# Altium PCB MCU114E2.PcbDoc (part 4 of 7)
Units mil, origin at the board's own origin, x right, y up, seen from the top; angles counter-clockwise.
Board outline 4153.94 x 2313.28 mil, 8 copper layers (Top Layer, GND 2, Signal Layer 3, Power 4, Power 5, Signal Layer 6, GND 7, Bottom), stack 61.2 mil thick; 444 components, 418 nets, 1811 pads, 981 vias.
Unrouted connection lines stored in the file: 3.
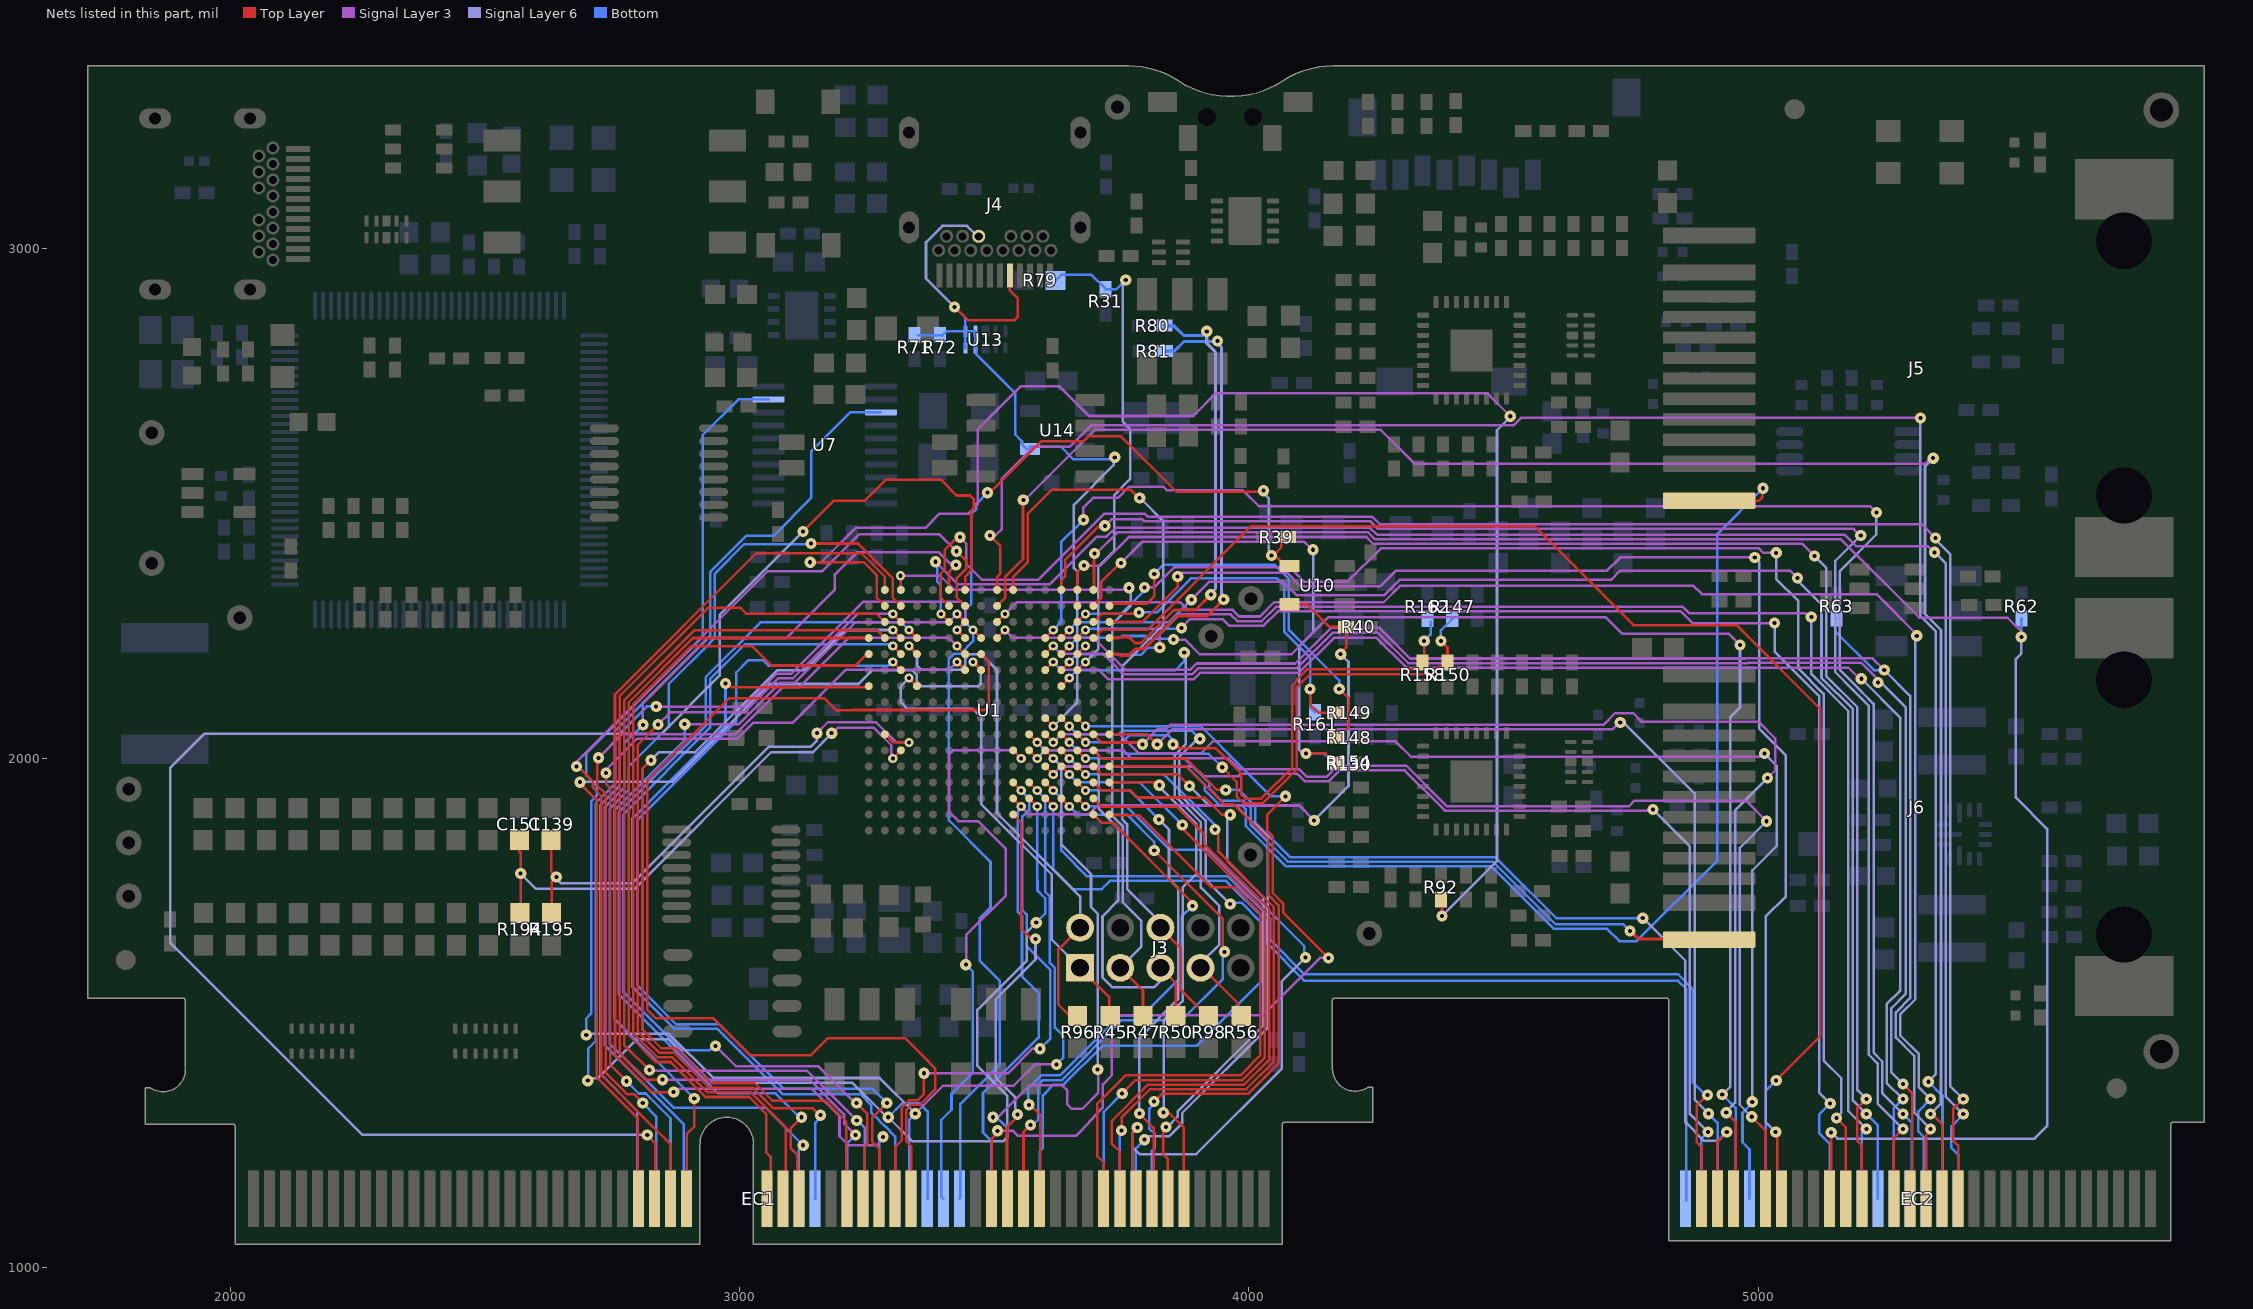
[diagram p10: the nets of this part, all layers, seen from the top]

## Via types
v1: diameter 22, hole 8, Top Layer to Bottom, tented both sides, 810 vias
v2: diameter 18, hole 8, Top Layer to Bottom, tented both sides, 153 vias
v3: diameter 19.68, hole 7.87, Top Layer to Bottom, tented both sides, 10 vias
v4: diameter 19.68, hole 7.87, Top Layer to Bottom, tented bottom, 4 vias
v5: diameter 19.68, hole 7.87, Top Layer to Bottom, tented top, 4 vias

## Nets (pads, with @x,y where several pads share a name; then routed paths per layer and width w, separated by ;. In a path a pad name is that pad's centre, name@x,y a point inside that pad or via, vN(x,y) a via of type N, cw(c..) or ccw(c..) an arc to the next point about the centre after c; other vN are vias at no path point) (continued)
MCU_C10C11_N: C139.1 R195.1 U1.K2 | length 1060.9
  Top Layer w4.9: C139.1@2630.06,1839.38 2630.06,1777.12 v1(2640.31,1766.88) 2631.04,1757.6 R195.1@2631.04,1695.94 ; U1.K2@3285.09,2047.04 3301.08,2031.06 v2(3332.6,2031.06)
  Signal Layer 3 w4.9: v1(3151.82,2049.25) 3173.14,2070.57 3268.21,2070.57 3307.73,2031.06 v2(3332.6,2031.06)
  Signal Layer 6 w4.9: v1(2640.31,1766.88) 2640.31,1763.7 2649.67,1754.34 2789.09,1754.34 3057.42,2022.67 3139.82,2022.67 3151.03,2033.89 3151.03,2048.47 v1(3151.82,2049.25)
MCU_C10C11_P: C151.1 R194.1 U1.L3 | length 1080.9
  Top Layer w4.9: C151.1@2567.97,1839.38 2567.97,1816.69 2570.31,1814.36 v1(2570.31,1773.88) 2570.31,1697.31 R194.1@2568.95,1695.94
  Top Layer w5: v2(3300.84,1999.8) U1.L3@3316.59,2015.55
  Signal Layer 3 w4.9: v1@3180.82,2048.25 3192.24,2059.67 3263.7,2059.67 3297.81,2025.56 3297.81,2009.22 3298.34,2008.69 3298.34,2003.35 3297.81,2002.83 v2(3300.84,1999.8)
  Signal Layer 6 w4.9: v1(2570.31,1773.88) 2600.74,1743.44 2793.61,1743.44 3061.94,2011.77 3144.34,2011.77 3180.82,2048.25 v1(3180.82,2049.25)
MCU_D_N: R81.2 U1.E16 | length 894.6
  Top Layer w6.1: U1.E16@3726.04,2204.52 3744.86,2204.52 3747.17,2202.22 3764.16,2202.22 3776.16,2214.22 3793.15,2214.22 3857.83,2278.9 3917.7,2278.9 v1(3950.26,2311.46)
  Signal Layer 6 w6.1: v1(3938,2819) 3938,2814.7 3946.29,2806.41 3946.29,2322.98 3947.22,2322.06 3947.22,2314.5 v1(3950.26,2311.46)
  Bottom w6.1: R81.2@3834.62,2799.19 3853.42,2799.19 3872.28,2818.04 3937.04,2818.04 v1(3938,2819)
MCU_D_P: R80.2 U1.D16 | length 866.5
  Top Layer w6.1: U1.D16@3726.04,2236.02 3745.16,2236.02 3747.46,2238.32 3764.16,2238.32 3776.16,2226.32 3788.14,2226.32 3852.82,2291 3895,2291 v1(3925,2321)
  Signal Layer 6 w6.1: v1(3917,2838) 3917,2814.47 3930.52,2800.95 3930.62,2800.95 3934.19,2797.38 3934.19,2332.52 3925,2323.33 v1(3925,2321)
  Bottom w6.1: R80.2@3833.62,2849 3852.42,2849 3871.28,2830.14 3909.14,2830.14 v1(3917,2838)
MCU_GPIO0: EC1.49 U1.F8 | length 1836.4
  Top Layer w5: v1(2687,1953) 2687,1950.57 2719.5,1918.07 2719.5,1374.3 2800.04,1293.75 2800.04,1136.68 EC1.49@2801.46,1135.27 ; v2(3458.32,2188.77) U1.F8@3474.07,2173.03
  Signal Layer 6 w5: v1(2687,1953) 2687.5,1953.5 2867.27,1953.5 3059.54,2145.77 3233.77,2145.77 3260.78,2172.78 3338.76,2172.78 3347.84,2163.7 3347.84,2151.35 3357.91,2141.28 3468.64,2141.28 3473.82,2146.46 3473.82,2173.27 v2(3458.32,2188.77)
MCU_GPIO1: EC1.51 U1.A7 | length 3651.8
  Top Layer w5: v1(2818.83,1260.64) 2834.33,1245.14 2834.33,1135.27 EC1.51@2832.95,1135.27 ; v1(3124.66,2445.11) 3184.72,2505.16 3245.53,2505.16 3287.36,2547 3395,2547 3426.23,2515.77 3452.4,2515.77 3459.33,2508.84 3459.33,2490.25 3454.65,2485.56 3454.65,2368.17 3442.57,2356.1 U1.A7@3442.57,2330.51
  Signal Layer 6 w5: v1(2818.83,1260.64) 2259.89,1260.64 1882,1638.53 1882,1981 1949,2048 2847,2048 2961,2162 2961,2281.44 v1(3124.66,2445.11)
MCU_GPIO2: EC1.53 U1.B7 | length 2009.9
  Top Layer w5: v1(2680,1984) 2682.48,1984 2711.5,1954.98 2711.5,1943 2728.5,1926 2728.5,1378.02 2833.07,1273.45 2833.55,1273.45 2864.45,1242.55 EC1.53@2864.45,1135.27 ; v1(3425.83,2406.27) 3445.33,2386.77 3445.33,2372.77 3426.54,2353.98 3426.54,2315.04 U1.B7@3442.57,2299.01
  Signal Layer 3 w5: v1(2680,1984) 2680,1992.46 3054.38,2366.84 3161.84,2366.84 3234.5,2439.5 3392.25,2439.5 3425.48,2406.27 v1(3425.83,2406.27)
MCU_GPIO3: EC1.55 U1.C7 | length 1706.8
  Top Layer w5: EC1.55@2895.94,1135.27 2895.94,1262.06 2911,1277.11 v1(2911,1332) ; v2(3426.83,2283.26) U1.C7@3442.57,2267.52
  Signal Layer 3 w5: v1(2892.27,2066.83) 2998.67,2066.83 3080.12,2148.27 3109.08,2148.27 3228.08,2267.27 3410.83,2267.27 v2(3426.83,2283.26)
  Bottom w5: v1(2892.27,2066.83) 2892.27,2035.36 2753.73,1896.82 2753.73,1489.27 v1(2911,1332)
MCU_GPIO4: EC1.50 U1.D7 | length 1825.8
  Top Layer w5: v2(3426.83,2251.77) U1.D7@3442.57,2236.02
  Signal Layer 3 w5: v1@2835,2101 3007.39,2101 3072.66,2166.27 3101.62,2166.27 3242.38,2307.03 3434.56,2307.03 3442.82,2298.76 3442.82,2276.84 3442.89,2276.78 3442.89,2267.83 v2(3426.83,2251.77)
  Bottom w5: EC1.50@2801.46,1135.27 2798.94,1137.78 2798.94,1308.06 2726.73,1380.27 2726.73,1908 2764.5,1945.77 2764.5,2048 2818.15,2101.65 v1(2836.25,2101.65)
MCU_GPIO5: EC1.52 U1.E7 | length 1754.2
  Top Layer w5: v1(2723.04,2000.8) 2720.5,1998.25 2720.5,1946.73 2737.5,1929.73 2737.5,1381.75 2778.63,1340.63 2792.37,1340.63 v1(2810,1323) ; v2(3426.83,2220.27) U1.E7@3442.57,2204.52
  Signal Layer 3 w5: v1(2723.04,2000.8) 2769.51,2047.27 2786.41,2047.27 2991.84,2047.27 3083.84,2139.27 3116.83,2139.27 3213.83,2236.27 3294.42,2236.27 3410.83,2236.27 v2(3426.83,2220.27)
  Bottom w5: v1(2810,1323) 2836.33,1296.67 2836.33,1138.65 EC1.52@2832.95,1135.27
MCU_GPIO6: EC1.54 U1.F7 | length 1701.2
  Top Layer w5: v1(2738,1971) 2738,1949 2746.5,1940.5 2746.5,1406 2746.5,1397.5 v1(2778,1366) ; v2(3426.83,2188.77) U1.F7@3442.57,2173.03
  Signal Layer 3 w5: v1(2738,1971) 2738,1977.44 2798.83,2038.27 2995.57,2038.27 3026.57,2069.27 3104.25,2069.27 3208.26,2173.27 3411.33,2173.27 v2(3426.83,2188.77)
  Bottom w5: v1(2778,1366) 2802.13,1341.87 2815.87,1341.87 2864.45,1293.3 EC1.54@2864.45,1135.27
MCU_GPIO7: EC1.56 U1.A6 | length 1889.5
  Top Layer w5: U1.A6@3411.08,2330.51 3411.08,2365.52 v1(3424.83,2379.27)
  Signal Layer 3 w5: v1(2810.25,2065.65) 2810.25,2108.25 2938.02,2236.02 3092.02,2236.02 3187,2331 3187,2360.91 3230.09,2404 3391.42,2404 3412.9,2382.52 3421.58,2382.52 v1(3424.83,2379.27)
  Bottom w5: v1(2810.25,2065.65) 2773.5,2028.9 2773.5,1942.04 2735.73,1904.27 2735.73,1436.27 2890,1282 2890,1141.21 EC1.56@2895.94,1135.27
MCU_GPIO8: EC1.57 U1.D1 | length 1683.9
  Top Layer w5: EC1.57@3053.43,1135.27 3061,1142.84 3061,1217.64 3052.13,1226.51 3052.13,1301.87 3019,1335 2933.48,1335 2864.74,1403.73 2835.04,1403.73 2782.5,1456.27 2782.5,1990.68 2782.5,2109.77 2908.75,2236.02 U1.D1@3253.6,2236.02
MCU_GPIO9: EC1.59 U1.E1 | length 1698.7
  Top Layer w5: EC1.59@3084.92,1135.27 3090.33,1140.68 3090.33,1276.4 3022.73,1344 2937.2,1344 2868.47,1412.73 2838.77,1412.73 2791.5,1460 2791.5,1986.96 2791.5,2106.04 2905.46,2220 3024.31,2220 3062.31,2182 3221.83,2182 3227.78,2182.03 3246.06,2200.31 3246.48,2200.31 3250.69,2204.52 U1.E1@3253.6,2204.52
MCU_GPIO10: EC1.61 U1.D4 | length 1799.4
  Top Layer w5: EC1.61@3116.42,1135.27 3112.83,1138.85 3112.83,1222.27 3100.83,1234.27 3100.83,1238.41 3100.83,1274.27 v1(3121.83,1295.27) ; v2(3332.34,2251.77) U1.D4@3348.09,2236.02
  Bottom w5: v1(3121.83,1295.27) 3117.23,1295.27 3070.5,1342 2958,1342 2762.73,1537.27 2762.73,1893.09 2933.33,2063.69 2933.33,2158.97 3041.63,2267.27 3316.84,2267.27 v2(3332.34,2251.77)
MCU_GPIO11: J3.2 R96.2 U1.E4 | length 1047.9
  Top Layer w5: v2(3332.34,2220.27) U1.E4@3348.09,2204.52 ; R96.2@3663.44,1497.68 3644.44,1497.68 3626,1516.12 3626,1624.85 J3.2@3668.52,1667.37
  Signal Layer 6 w5: v2(3332.34,2220.27) 3348.33,2204.27 3348.33,2182.35 3357.41,2173.27 3379.33,2173.27 3433.25,2173.27 3442.82,2182.85 3442.82,2195.19 3451.9,2204.27 3474.32,2204.27 3505.32,2173.27 3505.32,1891.99 3668.52,1728.79 J3.2@3668.52,1667.37
MCU_GPIO12: J3.1 R45.1 U1.G4 | length 931.4
  Top Layer w5: v2(3332.34,2157.28) U1.G4@3348.09,2141.53 ; J3.1@3668.52,1588.63 3725.59,1531.56 R45.1@3725.59,1499.18
  Signal Layer 6 w5: v2(3332.34,2157.28) 3316.59,2141.53 3316.59,2110.03 3329.57,2097.06 3457.83,2097.06 3474.32,2080.57 3474.32,1910.26 3612.83,1771.75 3612.83,1644.32 J3.1@3668.52,1588.63
MCU_GPIO13: J3.3 R47.1 U1.A3 | length 1401.6
  Top Layer w5: v2(3315.97,2358.24) 3315.97,2331.13 U1.A3@3316.59,2330.51 ; J3.3@3747.26,1588.63 3791.96,1543.93 R47.1@3791.96,1493.76
  Signal Layer 3 w5: v2(3315.97,2358.24) 3393.9,2358.24 3421.53,2330.61 3760.27,2330.61 v1(3764.22,2334.55)
  Signal Layer 6 w5: J3.3@3747.26,1588.63 3788.83,1630.2 3788.83,1680.93 3751.93,1717.83 3751.93,1866.87 3731.31,1887.49 3731.31,2262.95 3767.62,2299.26 v1@3767.62,2331.46
MCU_GPIO14: EC1.62 U1.B3 | length 2039.4
  Top Layer w5: v1(3140.37,2421.56) 3232.54,2421.56 3300.47,2353.63 3300.47,2315.13 U1.B3@3316.59,2299.01
  Bottom w5: EC1.62@3116.42,1135.27 3116.42,1231.85 v1(3124.83,1240.27) 3051.1,1314 2870.73,1314 2744.73,1440 2744.73,1900.55 2782.5,1938.32 2782.5,1983.5 2860.96,2061.96 2860.96,2125.96 2861,2126 2861,2145.75 2942.5,2227.25 2942.5,2227.77 2951.5,2236.77 2951.5,2362.5 3009.23,2420.23 3137.1,2420.23 v1@3137.71,2419.61
MCU_GPIO15: EC1.64 U1.C3 | length 1786.7
  Top Layer w5: v1(2840,2066) 2800.5,2026.5 2800.5,1983.23 2800.5,1463.73 2842.5,1421.73 2872.2,1421.73 2940.93,1353 3026.46,1353 3066.69,1312.77 3144.08,1312.77 3157.58,1299.27 v1(3158.83,1299.27) ; v2(3300.84,2283.26) U1.C3@3316.59,2267.52
  Signal Layer 3 w5: v1(2840,2066) 2864,2090 3009.12,2090 3076.39,2157.27 3105.35,2157.27 3231.34,2283.26 v2(3300.84,2283.26)
  Bottom w5: EC1.64@3147.91,1135.27 3148.33,1135.69 3148.33,1284.17 3158.83,1294.67 v1(3158.83,1299.27)
MCU_GPIO16: EC1.67 U1.D3 | length 1765.3
  Top Layer w5: v1(2826,1996) 2809.5,1979.5 2809.5,1467.46 2846.23,1430.73 2875.93,1430.73 2944.66,1362 3030.18,1362 3064.18,1328 3168.1,1328 3209.71,1286.39 3209.71,1136.47 EC1.67@3210.91,1135.27 ; v2(3300.84,2251.77) U1.D3@3316.59,2236.02
  Signal Layer 6 w5: v1(2826,1996) 2842,2012 2913.04,2012 3074.04,2173 3128.04,2173 3206.81,2251.77 v2(3300.84,2251.77)
MCU_GPIO17: EC1.69 U1.E3 | length 1850.2
  Top Layer w5: v1(3229.83,1323.27) 3250.33,1302.77 3250.33,1242.27 3245.33,1237.27 3245.33,1138.2 EC1.69@3242.4,1135.27 ; v2(3300.84,2220.27) U1.E3@3316.59,2204.52
  Signal Layer 3 w5: v1(2953,1435) 2992.5,1395.5 3154.05,1395.5 3226.28,1323.27 v1(3229.83,1323.27)
  Bottom w5: v1(2953,1435) 2949.57,1435 2941.57,1427 2885.73,1427 2771.73,1541 2771.73,1889.36 2942.33,2059.96 2942.33,2155.24 3010.86,2223.77 3291.41,2223.77 3292.42,2222.76 3298.35,2222.76 v2(3300.84,2220.27)
MCU_GPIO18: EC1.71 U1.F3 | length 1832.6
  Top Layer w5: EC1.71@3273.9,1135.27 3273.9,1233.72 3260.83,1246.79 3260.83,1294.83 v1(3289,1323) ; v2(3300.84,2188.77) U1.F3@3316.59,2173.03
  Bottom w5: v1(3289,1323) 3261.23,1350.77 3087.19,1350.77 2960.19,1477.77 2875.72,1477.77 2798.73,1554.76 2798.73,1878.18 2993.83,2073.28 2993.83,2168.83 3017.77,2192.77 3046.08,2192.77 3057.07,2181.78 3291.41,2181.78 3298.41,2188.77 v2(3300.84,2188.77)
MCU_GPIO19: R92.2 U1.B2 | length 2942.6
  Top Layer w5: v1(3138.64,2384.69) 3243.95,2384.69 3269.72,2358.92 3269.72,2324.14 3269.72,2314.39 U1.B2@3285.09,2299.01
  Top Layer w6.25: v1(4378.83,1690.27) 4378.83,1722.1 R92.2@4379.8,1723.06
  Signal Layer 3 w5: v1(3138.64,2384.69) 3160.34,2384.69 3227.65,2452 3364.56,2452 3392.83,2480.27 3449.35,2480.27 3467.33,2498.25 3467.33,2645.33 3551.84,2729.84 3627.91,2729.84 3685.98,2671.77 3890.61,2671.77 3935.61,2716.77 4467.33,2716.77 v1(4512.83,2671.27)
  Signal Layer 6 w5: v1(4378.83,1690.27) 4486.83,1798.27 4486.83,2643.84 4512.83,2669.84 v1(4512.83,2671.27)
MCU_GPIO20: EC1.68 U1.C2 | length 1976.5
  Top Layer w5: v1(2849,1369) 2817,1369 2767.43,1418.57 2764.5,1421.5 2764.5,2117.23 2764.73,2117.46 2764.73,2121.73 2938,2295 3002,2295 3013.36,2283.64 3268.97,2283.64 U1.C2@3285.09,2267.52
  Signal Layer 3 w5: v1(2849,1369) 3137.04,1369 3205.13,1300.91 3205.13,1282.97 v1(3227.81,1260.29)
  Bottom w5: EC1.68@3210.91,1135.27 3210.91,1243.38 v1(3227.81,1260.29)
MCU_GPIO21: EC1.70 U1.D2 | length 1931.3
  Top Layer w5: v1(2823,1388) 2773.5,1437.5 2773.5,2113.5 2911.39,2251.39 3269.72,2251.39 U1.D2@3285.09,2236.02
  Signal Layer 3 w5: v1(2823,1388) 2824.5,1386.5 3132.27,1386.5 3155.5,1363.27 v1(3230.08,1288.69)
  Bottom w5: v1(3230.08,1288.69) 3231.91,1288.69 3245.31,1275.29 3245.31,1138.18 EC1.70@3242.4,1135.27
MCU_GPIO22: EC1.72 U1.A2 | length 2158.1
  Top Layer w5: v1(2870.64,1344.76) 2828.51,1344.76 2755.5,1417.77 2755.5,1441.5 2755.5,2125.23 3032.74,2402.46 3238.91,2402.46 3285.09,2356.28 U1.A2@3285.09,2330.51
  Signal Layer 3 w5: v1(2870.64,1344.76) 2875.24,1344.76 2881.48,1351 3142.31,1351 3196.13,1297.18 3196.13,1257.97 3213.83,1240.27 3268.85,1240.27 3281.36,1252.78 v1(3281.36,1256.8)
  Bottom w5: EC1.72@3273.9,1135.27 3273.9,1249.34 v1(3281.36,1256.8)
MCU_GPIO23: EC1.74 U1.G1 | length 1725.4
  Top Layer w5: v1(2972.4,2146.85) 2977,2146.85 2984.67,2139.19 3245.3,2139.19 3245.58,2139.47 3251.54,2139.47 U1.G1@3253.6,2141.53
  Bottom w5: v1(2972.4,2146.85) 2972.4,2064.58 2789.73,1881.91 2789.73,1551.03 2871.99,1468.77 2956.46,1468.77 3084.46,1340.77 3237.08,1340.77 3258.21,1319.64 3258.21,1304.71 3274.33,1288.58 3274.33,1288.02 3284.58,1277.77 3285.15,1277.77 3305.39,1257.52 EC1.74@3305.39,1135.27
MCU_GPIO24: EC1.75 U1.E8 | length 2241.9
  Top Layer w5: EC1.75@3336.89,1135.27 3336.89,1238.21 3327.33,1247.77 3327.33,1309.52 3337.58,1319.77 3353.77,1319.77 3384,1350 3384,1391.16 3361.77,1413.4 3324.68,1450.48 3173.48,1450.48 3140.27,1417.27 3020.73,1417.27 2948.5,1489.5 2835.95,1489.5 2818.5,1506.96 2818.5,1956.5 2980.06,2118.06 3165.94,2118.06 3189.47,2094.53 3221.64,2094.53 3221.77,2094.66 3480.44,2094.66 3489.44,2103.67 3489.44,2189.15 U1.E8@3474.07,2204.52
MCU_GPIO25: J3.6 R98.2 U1.A10 | length 1548
  Top Layer w5: U1.A10@3537.06,2330.51 3537.06,2356.1 3565.33,2384.37 3565.33,2479.02 3613.58,2527.27 3767.43,2527.27 v1@3787.27,2507.43 ; J3.6@3826,1667.37 3866.44,1626.93 3866.44,1545.03 R98.2@3912.29,1499.18
  Signal Layer 6 w5: v1@3787.27,2507.43 3789.67,2507.43 3831.45,2465.65 3831.45,2261.01 3751.63,2181.19 3751.63,1879.9 3760.93,1870.59 3760.93,1743.07 3816.54,1687.46 3816.54,1665.95 J3.6@3825.44,1657.05
  other v1: 3785.44,2510.98
MCU_GPIO26: J3.5 R50.1 U1.L11 | length 878.4
  Top Layer w5: U1.L11@3568.56,2015.55 v2(3584.31,1999.8) ; J3.5@3826,1588.63 3856.25,1558.38 R50.1@3856.25,1493.76
  Signal Layer 6 w5: v2(3584.31,1999.8) 3600.3,2015.79 3694.79,2015.79 3705.31,2005.28 3705.31,1900.77 3742.93,1863.14 3742.93,1720.31 3712.38,1689.75 3712.38,1569.62 3731.73,1550.27 3813.83,1550.27 3826,1562.44 J3.5@3826,1588.63
MCU_GPIO27: J3.7 R56.1 U1.G13 | length 1100.1
  Top Layer w5: U1.G13@3631.55,2141.53 v2(3647.3,2157.28) ; J3.7@3904.74,1588.63 3908.47,1588.63 3979.08,1518.02 3979.08,1499.52 R56.1@3984.83,1493.76
  Signal Layer 6 w5: v1(3872.83,2207.27) 3875.92,2204.18 3875.92,2027.61 3854,2005.69 3854,1926.12 3868.33,1911.79 3905.73,1874.39 3905.73,1746.27 3941.83,1710.17 3941.83,1675.27 ; J3.7@3904.18,1578.31 3904.18,1597.06 3941.82,1634.69 3941.82,1675.26
  Bottom w5: v2(3647.3,2157.28) 3662.74,2172.72 3672.31,2172.72 3672.37,2172.78 3830.57,2172.78 ; 3830.58,2172.77 3855.52,2172.77 3872.83,2190.08 v1(3872.83,2207.27)
MCU_GPIO28: EC1.76 U1.N11 U7.9 | length 3236.3
  Top Layer w5: U1.N11@3568.56,1952.55 v2(3584.31,1936.81)
  Signal Layer 3 w5: v1(3344.83,1302.27) 3399.67,1357.11 3538,1357.11 3579.89,1399 v1(3622,1399)
  Signal Layer 6 w5: v1(2699,1457) 2701,1459 2861.83,1459 2948.56,1372.27 3274.83,1372.27 v1(3344.83,1302.27)
  Bottom w5: v1(2699,1457) 2699,1488.82 2708.73,1498.55 2708.73,1915.46 2719.5,1926.23 2719.5,1945.25 2699,1965.75 2699,2009.73 2928,2238.73 2928,2635 2997.57,2704.57 U7.9@3056.76,2704.57 ; EC1.76@3336.89,1135.27 3333.33,1138.83 3333.33,1290.77 v1(3344.83,1302.27) ; v2(3584.31,1936.81) 3599.81,1921.31 3599.81,1762.69 ; 3599.87,1762.69 3599.87,1737.96 3609.06,1728.77 3609.06,1598.33 3619,1588.38 3619,1471.36 3635.5,1454.86 3635.5,1412.5 v1(3622,1399)
MCU_GPIO29: EC1.78 U1.P11 U7.13 | length 3576.2
  Top Layer w5: U1.P11@3568.56,1921.06 v2(3584.31,1905.31)
  Signal Layer 6 w5: v1@2703,1372 2721.82,1372 2797.82,1448 2860.1,1448 2944.83,1363.27 3221.08,1363.27 3289.08,1295.27 v1(3291.83,1295.27) 3339.33,1247.77 3384.08,1247.77 3516.95,1247.77 3525.87,1256.68 3525.87,1337.17 3467,1396.04 3467,1506 3563.4,1602.4 3563.4,1658.21 v1(3582.37,1677.17)
  Bottom w5: v1@2703,1372 2703,1430 2717.73,1444.73 2717.73,1911.73 2755.5,1949.5 2755.5,2053.5 2942.5,2240.5 2942.5,2366.23 3012.93,2436.65 3066.19,2436.65 3141,2511.47 3141,2603 3216.98,2678.98 U7.13@3277.24,2678.98 ; v1(3291.83,1295.27) 3318.83,1322.27 3353.84,1322.27 3369.33,1306.78 3369.33,1260.02 3369.33,1136.21 EC1.78@3368.39,1135.27 ; v1(3582.37,1677.17) 3600.06,1694.86 3600.06,1725.04 3584.87,1740.23 3584.87,1760.29 3584.65,1760.51 3584.65,1904.96 v2(3584.31,1905.31)
  other v1: 2702,1367
MCU_GPIO30: EC1.80 U1.L10 | length 1181.3
  Top Layer w5: U1.L10@3537.06,2015.55 v2(3552.81,1999.8)
  Signal Layer 3 w5: v1@3444.83,1593.27 3444.83,1652.87 3522.83,1730.87 3522.83,1821.54 3467.85,1876.52 3429.52,1876.52 3411.33,1894.71 3411.33,2007.7 3418.92,2015.3 3537.31,2015.3 v2(3552.81,1999.8)
  Bottom w5: EC1.80@3399.88,1135.27 3395.91,1139.24 3395.91,1289.91 3416,1310 3416,1341 3458,1383 3458,1580.89 v1(3444.14,1594.74)
MCU_GPIO31: EC1.82 R39.1 U1.D8 U10.1 | length 2408.1
  Top Layer w5: v2(3458.32,2251.77) U1.D8@3474.07,2236.02 ; v1(3486.83,2521.27) 3491.77,2521.27 3592.81,2622.31 3675.09,2622.31 3684.78,2632 3749.1,2632 3857.97,2523.13 4026.41,2523.13 v1(4028.53,2525.25) ; v1(4044,2398) v1@4047.56,2398 ; R39.1@4076.49,2428.69 4072.6,2428.69 4063.29,2419.37 4063.29,2413.73 v1@4047.56,2398 ; U10.1@4079.74,2377.09 4071.86,2377.09 4054.2,2394.75 4050.82,2394.75 v1@4047.56,2398
  Signal Layer 6 w5: v1(4028.53,2525.25) 4028.53,2520.65 4039.09,2510.08 4039.09,2407.51 4044,2402.6 v1(4044,2398)
  Bottom w5: EC1.82@3431.38,1135.27 3433.33,1137.22 3433.33,1321.33 3511,1399 3511,1449.95 ; v1(3486.83,2521.27) 3464.83,2499.27 3464.83,2489.27 3454.83,2479.27 3454.83,2302.26 3442.82,2290.25 3442.82,2267.27 v2(3458.32,2251.77) 3458.32,2229.85 3433.25,2204.77 3420.9,2204.77 3410.83,2194.7 3410.83,1878.27 3492.59,1796.51 3492.59,1707.21 3471.83,1686.45 3471.83,1602.17 3511,1563 3511,1558.59 ; 3511.03,1449.98 3511.03,1558.56
MCU_GPIO32: EC1.85 U1.J14 | length 1886.5
  Top Layer w5: EC1.85@3495.44,1138.69 3495.44,1253.54 3506.49,1264.59 v1(3506.49,1268.65) ; U1.J14@3663.05,2078.54 v2(3678.79,2062.79) ; v1@4077.83,1931.27 4036,1889.44 4036,1857.35 4047,1846.35 4047,1734.99 4067,1714.99 4067,1697.01 v1(4155.91,1608.1)
  Signal Layer 3 w5: v1(3506.49,1268.65) 3506.75,1268.39 3536.71,1268.39 3546.33,1258.77 3660.77,1258.77 3670,1268 3711.68,1313.24 3713,1314.68 3713,1359.73 3731,1377.73 3731,1479.44 3746.83,1495.27 4026.83,1495.27 4139.66,1608.1 v1(4155.91,1608.1)
  Bottom w5: v2(3678.79,2062.79) 3905.53,2062.79 3986.15,1982.17 3986.15,1981.85 4011.66,1956.33 4011.99,1956.33 4043.05,1925.27 v1@4075.83,1925.27
  other v1: 4071.83,1925.27
MCU_GPIO33: EC1.87 U1.R10 | length 840.6
  Top Layer w5: EC1.87@3525.87,1135.27 3525.87,1276.87 v1@3550.12,1301.12 ; U1.R10@3537.06,1889.56 3552.81,1873.81 3552.81,1665.29 v1@3576.83,1641.27
  Signal Layer 6 w5: v1@3548.79,1300.77 3548.79,1304.41 3541,1312.2 3541,1334.76 3503.32,1372.45 3503.32,1527.32 3580.9,1604.9 v1(3580.9,1645.35) ; v1@3550.73,1304.37 v1@3553.83,1301.27
  other v1: 3545.73,1300.76
MCU_GPIO34: EC1.86 R40.1 U1.P10 U10.3 | length 2012.8
  Top Layer w5: U1.P10@3537.06,1921.06 v2(3552.81,1905.31) ; U10.3@4079.74,2302.28 4114.13,2302.28 4158.42,2258 R40.1@4190.66,2258 4190.66,2217.26 4180,2206.6 v1(4180,2204.3)
  Signal Layer 3 w5: v2(3552.81,1905.31) 3568.31,1889.81 3685.22,1889.81 3702.67,1907.27 4098.73,1907.27 v1(4128,1878)
  Signal Layer 6 w5: v1(4128,1878) 4195.33,1945.33 4195.33,2188.97 v1(4180,2204.3)
  Bottom w5: EC1.86@3494.37,1135.27 3494.37,1248.84 3477.88,1265.32 3477.88,1342.45 3587,1451.56 3587,1539 3554.4,1571.6 3554.4,1689.79 3546.31,1697.88 3546.31,1895.88 3552.81,1902.38 v2(3552.81,1905.31)
MCU_GPIO35: EC1.73 U1.N10 | length 1099.4
  Top Layer w5: EC1.73@3305.39,1135.27 3305.39,1236.83 3318.33,1249.77 3318.33,1313.25 3333.85,1328.77 3350.04,1328.77 3361.77,1340.49 v1(3361.77,1381.58) ; U1.N10@3537.06,1952.55 v2(3552.81,1936.81)
  Signal Layer 3 w5: v1(3361.77,1381.58) 3526.58,1381.58 3574.3,1429.3 3589.49,1429.3 v1(3589.87,1429.69)
  Bottom w5: v2(3552.81,1936.81) 3568.31,1921.31 3568.31,1911.73 3568.31,1898.89 3555.31,1885.89 3555.31,1701.61 3563.4,1693.51 3563.4,1665.81 3563.4,1631.25 3610,1584.66 3610,1449.81 v1(3589.87,1429.69)
MCU_GPIO36: EC2.122 U1.P12 | length 1937.9
  Top Layer w5: U1.P12@3600.06,1921.06 v2(3615.8,1905.31)
  Bottom w5: v2(3615.8,1905.31) 3615.8,1781.5 3654.12,1743.19 3711,1743.19 3727,1759.19 3955.19,1759.19 4033,1681.37 4033,1639.27 4109.27,1563 4842.56,1563 4857.87,1547.69 EC2.122@4857.87,1132.69
MCU_GPIO37: EC2.123 U1.N12 | length 1959.1
  Top Layer w5: U1.N12@3600.06,1952.55 v2(3615.8,1936.81) ; EC2.123@4889.05,1138.69 4889.05,1236.05 4878.83,1246.27 4878.83,1317.83 v1(4900,1339)
  Bottom w5: v2(3615.8,1936.81) 3631.55,1921.06 3631.55,1818.76 3682.12,1768.19 3958.91,1768.19 4042,1685.1 4042,1643 4109.31,1575.69 4842.6,1575.69 4870.83,1547.45 4870.83,1364.53 4896.36,1339 v1(4900,1339)
MCU_GPIO38: EC2.124 U1.M12 | length 2069.2
  Top Layer w5: U1.M12@3600.06,1984.05 v2(3615.8,1968.3)
  Signal Layer 3 w5: v2(3615.8,1968.3) 3631.3,1983.8 3891.55,1983.8 3910.58,1964.77 3979.6,1964.77 3984.6,1969.77 4094.54,1969.77 4109.71,1954.61 4155.64,1954.61 4177.31,1976.27 4305.29,1976.27 4384.37,1897.19 4782.75,1897.19 v1@4783.83,1898.27
  Signal Layer 6 w5: v1(4792.83,1899.27) 4865.57,1826.53 4865.57,1301.53 v1(4900.83,1266.27)
  Bottom w5: EC2.124@4887.98,1135.27 4887.98,1253.41 v1(4900.83,1266.27)
MCU_GPIO39: EC1.88 U1.L12 | length 1162.8
  Top Layer w5: U1.L12@3600.06,2015.55 v2(3615.8,1999.8)
  Signal Layer 3 w5: v1@3506.24,1295.7 3507.33,1295.7 3569.4,1357.77 3633.08,1357.77 3643.33,1347.52 3643.33,1320.67 3652,1312 3673,1312 3704,1343 3704,1388 v1(3703,1389)
  Signal Layer 6 w5: v2(3615.8,1999.8) 3631.8,1983.8 3631.8,1830.45 3689.83,1772.41 3689.83,1708.12 3703.38,1694.57 3703.38,1389.38 v1(3703,1389)
  Bottom w5: v1(3497.55,1295.32) 3504.57,1295.32 3518.97,1280.92 3524.43,1275.46 3524.43,1136.7 EC1.88@3525.87,1135.27
MCU_GPIO40: EC1.89 U1.P13 | length 1230.9
  Top Layer w5: EC1.89@3557.36,1135.27 3557.36,1266.24 v1(3571.12,1280) ; U1.P13@3631.55,1921.06 v2(3647.3,1905.31) ; v1(3814,1819) 3948.62,1684.38 3948.62,1631.43 3948.75,1631.3 3948.75,1623.25 v1(3952,1620)
  Bottom w5: v1@3573.19,1277.93 3586.33,1291.07 3586.33,1358.96 3595.64,1368.27 3632.56,1368.27 3750.09,1485.8 3867.97,1485.8 3948.62,1566.45 3948.62,1616.62 v1(3952,1620) ; v2(3647.3,1905.31) 3663.36,1889.25 3760.75,1889.25 3814,1836 v1(3814,1819)
MCU_GPIO41: EC1.91 U1.R15 | length 1032.6
  Top Layer w5: v1@3565.63,1324.51 3590.33,1299.81 3590.33,1136.74 EC1.91@3588.86,1135.27 ; U1.R15@3694.54,1889.56 3710.67,1873.44 3732.41,1873.44 v1@3885.58,1720.27
  Bottom w5: v1@3566.71,1320.27 3566.71,1352.06 3591.91,1377.27 3628.83,1377.27 3746.37,1494.8 3791.23,1494.8 3867.57,1571.14 3867.57,1689.01 v1(3888.83,1710.27)
  other v1: 3567.93,1319.66
MCU_GPIO44: J4.A5 J4.B5 R71.2 R72.2 U1.J12 U13.4 U13.5 U13.6 U13.7 U14.4 | length 1765.9
  Top Layer w5: v1(3422,2886) 3448,2860 3540,2860 3546,2866 3546,2903 3530.53,2918.47 J4.A5@3530.53,2947.46 ; U1.J12@3600.06,2078.54 v2(3615.8,2062.79)
  Signal Layer 6 w5: v1(3422,2886) 3366,2942 3366,3012.82 3392.17,3038.99 3398.11,3044.93 3446.41,3044.93 3466.71,3024.63 J4.B5@3469.5,3024.63 ; v2(3615.8,2062.79) 3663.29,2110.28 3663.29,2366.06 3656.33,2373.02 3656.33,2497.33 3734.42,2575.42 3734.42,2586.42 v1@3737,2589
  Bottom w5: R71.2@3350.58,2830.54 3398.58,2830.54 3406.03,2838 U13.6@3443.32,2838 ; v1(3422,2886) 3443.32,2864.69 U13.6@3443.32,2838 ; U13.5@3443.32,2805.13 U13.6@3443.32,2838 ; U14.4@3563.71,2606.6 3554.4,2615.91 3554.4,2622.06 3541.5,2634.96 3541.5,2716.25 3464.44,2793.31 3464.44,2803.69 U13.4@3463,2805.13 U13.7@3463,2838 U13.6@3443.32,2838 ; U14.4@3569.87,2606.6 3569.87,2611.5 3630.5,2611.5 3654.71,2587.29 3735.29,2587.29 v1@3737,2589
  other v1: 3736.48,2590.64
MCU_GPIO45: EC1.92 U1.J13 | length 1598.7
  Top Layer w5: U1.J13@3631.55,2078.54 v2(3647.3,2062.79)
  Signal Layer 6 w5: v1(3903.44,2038.11) 3899.15,2038.11 3863,2001.96 3863,1929.85 3914.73,1878.12 3914.73,1762.27 v1(3963,1714)
  Bottom w5: EC1.92@3588.86,1135.27 3588.86,1228.57 3595.33,1235.04 3595.33,1338.33 3616.27,1359.27 3636.29,1359.27 3713.02,1436 3898,1436 4022.71,1560.71 4022.71,1678.94 3985,1716.64 3965.64,1716.64 v1(3963,1714) ; v2(3647.3,2062.79) 3662.8,2047.29 3745.13,2047.29 3751.63,2053.79 3887.76,2053.79 v1(3903.44,2038.11)
MCU_GPIO46: R31.2 R79.1 U1.F14 | length 979.6
  Top Layer w5: U1.F14@3663.05,2173.03 v2(3678.79,2188.77)
  Signal Layer 6 w5: v2(3678.79,2188.77) 3703.83,2213.81 3703.83,2375.72 3735.1,2407 3735.1,2516.1 3766.83,2547.83 3766.83,2645.98 3752.42,2660.4 3752.42,2698.67 3752.5,2698.75 3752.5,2713.25 3752.42,2713.33 3752.42,2928.82 3758,2934.4 v1(3758,2939)
  Bottom w5: R79.1@3620.32,2937.82 3631.5,2949 3690.69,2949 3718,2921.69 R31.2@3718,2920.62 3739.62,2920.62 v1(3758,2939)
MCU_GPIO47: U1.E14 | length 22.3
  Top Layer w5: U1.E14@3663.05,2204.52 v2(3678.79,2220.27)
MCU_GPIO48: EC1.99 U1.R16 | length 1206.9
  Top Layer w5: EC1.99@3714.84,1135.27 3714.84,1206.16 3702.25,1218.75 3702.25,1321.97 3757.54,1377.27 3983.21,1377.27 4022,1416.06 4022,1696.35 3971.35,1747 3925.57,1747 3784.3,1888.27 3727.33,1888.27 U1.R16@3726.04,1889.56
MCU_GPIO49: EC1.101 U1.P15 | length 1260.2
  Top Layer w5: U1.P15@3694.54,1921.06 3710.67,1904.94 3858.06,1904.94 3911.83,1851.17 3911.83,1831.98 4040,1703.81 4040,1408.6 3990.67,1359.27 3801.84,1359.27 3731,1288.42 3731,1243.1 3746.34,1227.76 EC1.101@3746.34,1135.27
MCU_GPIO50: EC1.103 U1.P14 | length 1383.5
  Top Layer w5: U1.P14@3663.05,1921.06 v2(3678.79,1905.31) ; EC1.103@3777.83,1135.27 3771.33,1141.77 3771.33,1265.77 v1(3780.83,1275.27)
  Signal Layer 6 w5: v1(3780.83,1275.27) 3780.83,1272.84 3771.83,1263.84 3771.83,1236.27 3785.33,1222.77 3834.06,1222.77 3846.58,1222.77 3896.5,1222.77 4064,1390.27 4064,1562 v1(4111,1609)
  Bottom w5: v2(3678.79,1905.31) 3759.69,1905.31 3844.92,1820.08 3919.75,1820.08 4108.46,1631.37 4108.46,1611.54 v1(4111,1609)
MCU_GPIO51: EC1.105 U1.N14 | length 995
  Top Layer w5: U1.N14@3663.05,1952.55 v2(3678.79,1936.81) ; v1(3784.93,1302.64) 3784.93,1302.17 3812.96,1274.14 3812.96,1138.89 EC1.105@3809.33,1135.27
  Signal Layer 6 w5: v1(3784.93,1302.64) 3784.93,1451.1 3860.86,1527.03 3860.86,1744.99 3843,1762.85 3843,1860 v1(3823,1880)
  Bottom w5: v2(3678.79,1936.81) 3766.19,1936.81 3799.97,1903.03 v1(3823,1880)
MCU_GPIO52: EC1.107 U1.N15 | length 1162.9
  Top Layer w5: U1.N15@3694.54,1952.55 3710.29,1936.81 3767.19,1936.81 3781.06,1922.94 3888.41,1922.94 3888.58,1922.77 3913.33,1922.77 3946.99,1889.11 v1(3963.03,1889.11) ; v1(3836.83,1276.27) 3836.83,1271.67 3831.41,1266.25 3831.41,1222.68 3840.83,1213.27 EC1.107@3840.83,1135.27
  Signal Layer 6 w5: v1(3836.83,1276.27) 3839.81,1276.27 3859.83,1296.29 3859.83,1306.83 4028,1475 4028,1727.82 3957.26,1798.57 3957.26,1884.34 v1@3955.33,1886.27
MCU_GPIO53: EC1.109 U1.N16 | length 992.2
  Top Layer w5: U1.N16@3726.04,1952.55 3813.85,1952.55 3819.4,1947 v1(3824,1947) ; v1(3831.83,1304.27) 3834.41,1301.69 3845.42,1301.69 3872.32,1274.79 EC1.109@3872.32,1135.27
  Signal Layer 6 w5: v1(3824,1947) 3824,1943.39 3896.73,1870.66 3896.73,1773.25 3869.88,1746.4 3869.88,1523.32 3832.57,1486.01 3832.57,1305.01 v1(3831.83,1304.27)
MCU_GPIO54: EC1.100 U1.M13 | length 1339.7
  Top Layer w5: U1.M13@3631.55,1984.05 v2(3647.3,1968.3) ; v1(3751,1342) 3777.27,1368.27 3986.94,1368.27 4031,1412.33 4031,1700.08 3869.12,1861.96 v1(3869.12,1868.69)
  Bottom w5: v2(3647.3,1968.3) 3662.74,1952.87 3672.31,1952.87 3672.37,1952.8 3685.21,1952.8 3685.28,1952.87 3784.94,1952.87 v1(3869.12,1868.69) ; EC1.100@3714.84,1135.27 3714.84,1305.84 v1(3751,1342)
MCU_GPIO55: EC1.102 U1.M14 | length 1335.2
  Top Layer w5: U1.M14@3663.05,1984.05 v2(3678.79,1968.3) ; v1(3750,1269) 3750,1294.7 3805.57,1350.27 3994.39,1350.27 4049,1404.87 4049,1707.53 3939.76,1816.78 v1@3939.76,1855.75
  Bottom w5: v2(3678.79,1968.3) 3833.45,1968.3 3934.8,1866.95 3934.8,1865.31 3939.76,1860.35 v1@3939.76,1855.75 ; EC1.102@3746.34,1135.27 3746.34,1260.74 3750,1264.4 v1(3750,1269)
  other v1: 3933.38,1859.84
MCU_GPIO56: EC1.104 U1.M15 | length 1241.2
  Top Layer w5: U1.M15@3694.54,1984.05 3710.29,1968.3 3860.64,1968.3 v1(3883.37,1945.57)
  Signal Layer 6 w5: v1(3794.83,1251.27) 3801.33,1257.77 3843.33,1257.77 3868.83,1283.27 3868.83,1303.1 4037,1471.27 4037,1844.1 3973.83,1907.27 3921.67,1907.27 v1(3883.37,1945.57)
  Bottom w5: EC1.104@3777.83,1135.27 3777.83,1234.27 v1(3794.83,1251.27)
MCU_GPIO57: EC1.106 U1.M16 | length 1296.7
  Top Layer w5: U1.M16@3726.04,1984.05 3876.8,1984.05 3951.08,1909.77 3969.57,1909.77 4038,1841.33 4038,1731.26 4058,1711.26 4058,1401.15 3998.12,1341.27 3828.89,1341.27 v1(3813.53,1325.9)
  Bottom w5: EC1.106@3809.33,1135.27 3809.33,1229.53 3815.07,1235.27 3815.07,1262.27 3804,1273.34 3804,1311.77 3813.53,1321.3 v1(3813.53,1325.9)
MCU_GPIO58: J5.12 U1.L13 | length 2427.3
  Top Layer w5: U1.L13@3631.55,2015.55 v2(3647.3,1999.8) ; J5.12@4903.31,2505.45 5001.01,2505.45 5007.06,2511.5 5007.06,2528.06 v1(5009,2530)
  Bottom w5: v2(3647.3,1999.8) 3662.74,1984.36 3672.31,1984.36 3672.37,1984.3 3685.21,1984.3 3685.28,1984.36 3876.49,1984.36 3913.33,1947.52 3913.33,1936.77 3942.83,1907.27 3985.85,1907.27 3994,1899.12 3994,1866.54 4072.78,1787.77 4475.6,1787.77 4598.37,1665 4703,1665 4727,1641 4761,1641 4919.5,1799.5 4919.5,2440.5 v1(5009,2530)
MCU_GPIO59: J6.12 U1.L14 | length 1419.6
  Top Layer w5: U1.L14@3663.05,2015.55 v2(3678.79,1999.8)
  Top Layer w6.25: v1(4748,1661) 4763.73,1645.27 4901.83,1645.27 J6.12@4903.31,1643.8
  Bottom w5: v2(3678.79,1999.8) 3873.78,1999.8 3922.33,1951.25 3922.33,1940.5 3946.56,1916.27 3989.58,1916.27 4003,1902.85 4003,1870.27 4076.5,1796.77 4479.33,1796.77 4602.1,1674 4735,1674 v1(4748,1661)
MCU_GPIO60: EC2.125 U1.L15 | length 1911.3
  Top Layer w5: U1.L15@3694.54,2015.55 3710.67,1999.42 3875.93,1999.42 3900.33,1975.02 3937.51,1937.84 v1(3954.35,1937.84) ; EC2.125@4919.47,1135.27 4919.47,1247.91 v1(4937.83,1266.27)
  Signal Layer 6 w5: v1(4773,1686) 4856.57,1602.43 4856.57,1285.79 4893.58,1248.77 4920.33,1248.77 v1(4937.83,1266.27)
  Bottom w5: v1(3954.35,1937.84) 3980.73,1937.84 4012,1906.58 4012,1874 4080.23,1805.77 4483.06,1805.77 4503.56,1785.27 4503.88,1785.27 4603.15,1686 v1(4773,1686)
MCU_GPIO61: EC2.126 U1.K16 | length 2046.8
  Top Layer w5: U1.K16@3726.04,2047.04 3800.06,2047.04 v1(3819.83,2027.27)
  Signal Layer 3 w5: v1(3819.83,2027.27) 3849.14,2056.58 4713.39,2056.58 4727.08,2070.27 v1(4728.83,2070.27)
  Signal Layer 6 w5: v1(4728.83,2070.27) 4733.43,2070.27 4738.34,2065.36 4740.08,2065.36 4809.88,1995.56 4874.57,1930.88 4874.57,1329.79 4901.83,1302.52 v1(4901.83,1302.27)
  Bottom w5: v1(4901.83,1302.27) 4919.83,1284.27 4919.83,1135.63 EC2.126@4919.47,1135.27
MCU_GPIO62: EC2.127 U1.K15 | length 2345.4
  Top Layer w5: U1.K15@3694.54,2047.04 3710.67,2030.92 3787.18,2030.92 v1(3790.83,2027.27) ; v1(4936.83,1304.27) 4955.33,1285.77 4955.33,1139.63 EC2.127@4950.97,1135.27
  Signal Layer 3 w5: v1(3790.83,2027.27) 3821.56,2058 3837.83,2058 3845.41,2065.58 4696.14,2065.58 4718.83,2088.27 4754.7,2088.27 4771.7,2071.27 5000.83,2071.27 5033,2039.1 5033,1976.44 v1(5017.83,1961.27)
  Signal Layer 6 w5: v1(4936.83,1304.27) 4936.83,1306.52 4954.33,1324.02 4954.33,1897.77 v1(5017.83,1961.27)
MCU_GPIO63: R158.1 R162.2 U1.K14 | length 1064.7
  Top Layer w5: U1.K14@3663.05,2047.04 v2(3678.79,2031.29) v2@3673.61,2036.48 ; v1(3850.83,2027.27) 3855.43,2027.27 3862.66,2020.04 3934.43,2020.04 3984.83,1969.64 3984.83,1928.7 3992.76,1920.77 4023.7,1920.77 4085,1982.06 4085,2143.13 4094,2152.13 4094,2154.41 4114.05,2174.46 4328.59,2174.46 4328.77,2174.64 4331.52,2174.64 R158.1@4337.92,2181.04 ; R158.1@4340.83,2187.89 4343.83,2190.89 v1(4343.83,2230.27)
  Bottom w5: v2(3678.79,2031.29) 3750.82,2031.29 3764.31,2044.79 3842.19,2044.79 3850.83,2036.15 v1(3850.83,2027.27) ; v1(4343.83,2230.27) 4343.95,2230.27 4356.44,2242.76 R162.2@4356.44,2267.7
MCU_GPIO64: R147.2 R150.1 U1.K13 | length 1139.8
  Top Layer w5: U1.K13@3631.55,2047.04 v2(3647.3,2031.29) ; v1(3947.45,1982.27) 3975.83,1953.89 3975.83,1924.97 3989.03,1911.77 4027.43,1911.77 4094,1978.34 4094,2139.41 4119.24,2164.64 4358.36,2164.64 4373.28,2179.57 4381.34,2179.57 R150.1@4389.66,2187.89 4389.66,2217.44 v1(4376.83,2230.27)
  Bottom w5: v2(3647.3,2031.29) 3663.29,2015.3 3751.63,2015.3 3758.13,2008.8 3920.92,2008.8 v1(3947.45,1982.27) ; v1(4376.83,2230.27) 4376.83,2251.21 R147.2@4399,2273.38
MCU_GPIO65: EC2.130 U1.K12 | length 2382.7
  Top Layer w5: U1.K12@3600.06,2047.04 v2(3615.8,2031.29)
  Signal Layer 3 w5: v2(3615.8,2031.29) 3631.3,2046.79 3746.56,2046.79 3780.69,2012.66 3783.58,2009.77 3905.89,2009.77 3929.84,2033.73 4287.02,2033.73 4317.47,2003.27 5001.23,2003.27 5007.23,2009.27 v1(5011.83,2009.27)
  Signal Layer 6 w5: v1(4987.83,1325.58) 4987.83,1779.83 5036,1828 5036,1985.1 v1(5011.83,2009.27)
  Bottom w5: EC2.130@4982.46,1135.27 4982.46,1232.39 4968.71,1246.14 4968.71,1303.78 4987.83,1322.9 v1(4987.83,1325.58)
MCU_GPIO66: EC2.131 U1.K11 | length 2328.4
  Top Layer w5: U1.K11@3568.56,2047.04 v2(3584.31,2031.29) ; v1(4986.83,1296.27) 5013.96,1269.14 EC2.131@5013.96,1135.27
  Signal Layer 3 w5: v2(3584.31,2031.29) 3600.3,2015.3 3754.07,2015.3 3769.57,1999.8 3960.3,1999.8 3981.33,1978.77 4098.27,1978.77 4113.43,1963.61 4151.92,1963.61 4173.58,1985.27 4309.01,1985.27 4388.1,1906.19 4746.4,1906.19 4756.98,1916.77 4975.33,1916.77 v1(5015.83,1876.27)
  Signal Layer 6 w5: v1(4986.83,1296.27) 4963.33,1319.77 4963.33,1823.77 v1(5015.83,1876.27)
MCU_GPIO67: EC2.132 U1.D15 | length 2672.2
  Top Layer w5: U1.D15@3694.54,2236.02 3710.67,2252.14 3800.45,2252.14 4004.08,2455.77 4560.1,2455.77 4754.6,2261.27 4956.83,2261.27 5121,2097.1 5121,1453.44 v1(5034.83,1367.27)
  Bottom w5: EC2.132@5013.96,1135.27 5013.96,1346.4 v1(5034.83,1367.27)
MCU_GPIO68: EC2.133 U1.C16 | length 2658.5
  Top Layer w5: U1.C16@3726.04,2267.52 3791.08,2267.52 3860,2336.44 v1(3860,2357) ; v1@5037.13,1258.37 5037.13,1143.59 EC2.133@5045.46,1135.27
  Signal Layer 3 w5: v1(3860,2357) 3867.32,2364.32 4074.55,2364.32 4101.33,2337.54 4257.65,2337.54 4288.38,2368.27 4702.83,2368.27 4728.83,2394.27 v1(4992.83,2394.27)
  Signal Layer 6 w5: v1(4992.83,2394.27) 5001.83,2385.27 5001.83,2057.54 5036.33,2023.04 5054,2005.37 5054,1729 5014,1689 5014,1523.27 5014.33,1522.94 5014.33,1317.29 5014,1316.96 5014,1286.1 v1(5033.83,1266.27)
MCU_GPIO69: R148.1 U1.B16 | length 794.9
  Top Layer w5: U1.B16@3726.04,2299.01 3728.95,2299.01 3733.7,2303.77 3800.08,2303.77 3813.95,2317.64 v1(3813.95,2361.54) ; R148.1@4172.26,2040.56 4176.2,2040.56 4185.51,2049.87 4185.51,2050.48 4195.51,2060.48 4195.51,2117.72 v1(4177.16,2136.07)
  Bottom w5: v1(3813.95,2361.54) 3832.4,2380 4050,2380 4078.33,2351.67 4078.33,2251.77 4177.16,2152.94 v1(4177.16,2136.07)
MCU_GPIO70: R149.1 R161.2 U1.C15 | length 778.7
  Top Layer w5: U1.C15@3694.54,2267.52 3710.29,2283.26 3780.83,2283.26 v1(3783.83,2286.27) ; v1(4120,2136) 4120,2105.91 4136.47,2089.45 R149.1@4172.26,2089.45
  Bottom w5: v1(3783.83,2286.27) 3819.27,2286.27 3885.93,2352.93 4055.17,2352.93 4069.33,2338.77 4069.33,2248.04 4120,2197.37 v1(4120,2136) 4120.52,2135.48 4120.52,2099.63 R161.2@4129.83,2090.31
MCU_GPIO71: R130.1 R154.1 U1.B15 | length 1075.4
  Top Layer w5: U1.B15@3694.54,2299.01 3709.92,2314.39 3709.92,2345.67 3747.25,2383 v1(3749,2383) ; v1(4111.77,2009.39) 4150.61,2009.39 4168.32,1991.68 R154.1@4172.26,1991.68 ; R154.1@4180.88,1994.02 R154.1@4184.81,1994.02
  Signal Layer 3 w5: v1(3749,2383) 3791.27,2425.27 4108.4,2425.27 4124.4,2409.27 v1(4125.83,2409.27)
  Signal Layer 6 w5: v1@4114.76,2001.09 4098.33,2017.52 4098.33,2218.97 4125.83,2246.47 v1(4125.83,2409.27)
  Bottom w5: v1(4111.77,2009.39) 4146.74,2009.39 4167.8,1988.33 R130.1@4171.74,1988.33
MCU_GPIO72: EC2.139 R62.1 U1.A15 | length 3596.8
  Top Layer w5: U1.A15@3694.54,2330.51 3695.77,2331.74 3695.77,2400.77 v1(3697,2402) ; EC2.139@5139.94,1135.27 5142.83,1138.15 v1(5142.83,1265.27)
  Signal Layer 3 w5: v1(3697,2402) 3700.18,2402 3741.44,2443.27 4234.1,2443.27 4247.6,2429.77 5161.81,2429.77 5315.81,2275.77 5489.23,2275.77 5516,2249 v1(5516,2238)
  Signal Layer 6 w5: v1(5142.83,1265.27) 5154.83,1253.27 5542.27,1253.27 5566.83,1277.83 5566.83,1861.17 5505.37,1922.63 5505.37,2194.78 5516,2205.42 v1(5516,2238)
  Bottom w5: v1(5516,2238) R62.1@5516,2274.38
MCU_GPIO73: EC2.140 U1.D14 | length 2603.7
  Top Layer w5: U1.D14@3663.05,2236.02 v2(3678.79,2251.77)
  Signal Layer 3 w5: v1(3867.32,2255.76) 3867.32,2256.06 3884.53,2273.27 3947.83,2273.27 3960.83,2260.27 4028.72,2260.27 4056.63,2288.17 4847.93,2288.17 4870.83,2265.27 v1(5031.83,2265.27)
  Signal Layer 6 w5: v1(5031.83,2265.27) 5031.83,2209.54 5119,2122.37 5119,1344.1 v1(5140.83,1322.27)
  Bottom w5: v2(3678.79,2251.77) 3681.28,2254.25 3865.82,2254.25 v1(3867.32,2255.76) ; EC2.140@5139.94,1135.27 5139.94,1243.41 5119,1264.35 5119,1300.44 v1(5140.83,1322.27)
MCU_GPIO74: EC2.141 U1.C14 | length 2793.2
  Top Layer w5: U1.C14@3663.05,2267.52 v2(3678.79,2283.26) ; v1(5153,1294) 5171.44,1275.56 EC2.141@5171.44,1135.27
  Signal Layer 3 w5: v1(3794.59,2335.4) 3813.65,2335.4 3853.56,2375.3 4079.16,2375.3 4107.92,2346.54 4193.54,2346.54 4258.77,2411.77 5001,2411.77 5009.5,2403.27 v1(5034.83,2403.27)
  Signal Layer 6 w5: v1(5034.83,2403.27) 5034.83,2352.27 5078.37,2308.73 5078.37,2175.73 5128,2126.1 5128,1406.75 5162.56,1372.19 5162.56,1303.56 v1(5153,1294)
  Bottom w5: v2(3678.79,2283.26) 3748.73,2283.26 v1@3797.73,2332.26
MCU_GPIO75: U1.B14
MCU_GPIO76: EC2.143 U1.A14 | length 2840.6
  Top Layer w5: U1.A14@3663.05,2330.51 3663.05,2365.48 v1(3675.83,2378.27) ; EC2.143@5202.94,1135.27 5202.94,1240.16 5194.33,1248.77 5194.33,1313.44 v1(5211.83,1330.94)
  Signal Layer 3 w5: v1(3675.83,2378.27) 3708.13,2378.27 3764.13,2434.27 4230.38,2434.27 4243.88,2420.77 5086.23,2420.77 v1(5110,2397)
  Signal Layer 6 w5: v1(5110,2397) 5132.83,2374.17 5132.83,2161.54 5194.33,2100.04 5194.33,1348.43 v1(5211.83,1330.94)
MCU_GPIO77: EC2.144 U1.F13 | length 2751
  Top Layer w5: U1.F13@3631.55,2173.03 v2(3647.3,2188.77)
  Signal Layer 3 w5: v1(3824.83,2217.27) 3824.83,2243.02 3864.08,2282.27 3964,2282.27 3977,2269.27 4025,2269.27 4052.9,2297.17 4851.65,2297.17 4864.64,2284.19 4981.57,2284.19 4981.65,2284.27 5092.32,2284.27 5099.32,2277.27 v1(5103.83,2277.27)
  Signal Layer 6 w5: v1(5103.83,2277.27) 5103.83,2165.08 5176.33,2092.58 5176.33,1307.77 v1(5211.83,1272.27)
  Bottom w5: v2(3647.3,2188.77) 3662.8,2204.27 3747.93,2204.27 3749.44,2202.77 3787.77,2202.77 3802.27,2217.27 v1(3824.83,2217.27) ; EC2.144@5202.94,1135.27 5202.94,1263.37 v1(5211.83,1272.27) ; v1@5212.83,1271.27 v1@5213.83,1272.27
MCU_GPIO78: EC2.128 U1.E13 | length 2531.9
  Top Layer w5: U1.E13@3631.55,2204.52 v2(3647.3,2220.27)
  Signal Layer 3 w5: v1(3852,2233) 3874.1,2233 3902.93,2204.17 4083.53,2204.17 4156.36,2277 4699.75,2277 4732.28,2244.47 4941.63,2244.47 v1(4963.83,2222.27)
  Signal Layer 6 w5: v1(4929,1340) 4929.96,1340 4944.33,1354.37 4944.33,2080.33 4963.83,2099.83 v1(4963.83,2222.27)
  Bottom w5: v2(3647.3,2220.27) 3663.29,2236.27 3747.93,2236.27 3751.63,2239.96 3796.03,2239.96 3801.23,2234.77 3850.23,2234.77 v1(3852,2233) ; v1(4929,1340) 4955.33,1313.67 4955.33,1135.27 EC2.128@4950.97,1135.27
MCU_GPIO79: EC2.146 U1.D13 | length 2811.6
  Top Layer w5: U1.D13@3631.55,2236.02 v2(3647.3,2251.77)
  Signal Layer 3 w5: v1(3886.83,2311.27) 3921.88,2346.32 4067.1,2346.32 4093.87,2319.54 4265.1,2319.54 4295.83,2350.27 4710.29,2350.27 4727.79,2367.77 5062.75,2367.77 v1(5076.83,2353.69)
  Signal Layer 6 w5: v1(5076.83,2353.69) 5076.83,2348.48 5103.12,2322.19 5123.83,2301.48 5123.83,2157.81 5185.33,2096.31 5185.33,1328.1 v1(5211.83,1301.6)
  Bottom w5: v2(3647.3,2251.77) 3662.8,2267.27 3685.21,2267.27 3685.28,2267.2 3842.77,2267.2 v1(3886.83,2311.27) ; v1(5211.83,1301.6) 5234.43,1279 EC2.146@5234.43,1135.27
MCU_GPIO80: EC2.147 U1.A13 | length 3055.2
  Top Layer w5: U1.A13@3631.55,2330.51 3631.55,2349.35 3639.05,2356.85 3639.05,2389.49 3703.32,2453.76 3714.45,2453.76 v1(3716.97,2456.27) ; EC2.147@5265.93,1135.27 5265.93,1254.37 v1(5283.83,1272.27)
  Signal Layer 3 w5: v1(3716.97,2456.27) 3729.7,2469 3790.62,2469 3794.85,2464.77 4238.54,2464.77 4253.04,2450.27 5186.9,2450.27 5199.9,2437.27 v1(5200.83,2437.27)
  Signal Layer 6 w5: v1(5200.83,2437.27) 5150.83,2387.27 5150.83,2169.54 5187,2133.37 5187,2132.83 5217,2102.83 5217,1418 5233.83,1401.17 5233.83,1322.27 v1(5283.83,1272.27)
MCU_GPIO81: EC2.148 U1.F12 | length 2774.2
  Top Layer w5: U1.F12@3600.06,2173.03 v2(3615.8,2188.77)
  Signal Layer 3 w5: v2(3615.8,2188.77) 3631.3,2173.27 3640.88,2173.27 3705.84,2173.27 3724.34,2154.77 3891.22,2154.77 3904.46,2168 4098.27,2168 4166.62,2236.35 4250.29,2236.35 4308.87,2177.77 4982.26,2177.77 4982.49,2178 5176.3,2178 5198.3,2156 v1(5202,2156)
  Signal Layer 6 w5: v1(5202,2156) 5278.83,2079.17 5278.83,1544.27 5276.83,1542.27 5251.83,1517.27 5251.83,1362.94 v1(5283.83,1330.94)
  Bottom w5: EC2.148@5265.93,1135.27 5265.93,1313.03 v1(5283.83,1330.94)
MCU_GPIO82: EC2.149 U1.E12 | length 2812
  Top Layer w5: U1.E12@3600.06,2204.52 v2(3615.8,2220.27) ; v1(5283.83,1360.27) 5302.33,1341.77 5302.33,1140.17 EC2.149@5297.43,1135.27
  Signal Layer 3 w5: v2(3615.8,2220.27) 3631.3,2204.77 3713.6,2204.77 3727.8,2190.57 3753.87,2164.5 3888.23,2164.5 3900.73,2177 4094.54,2177 4163.73,2246.19 4253.18,2246.19 4312.6,2186.77 4978.54,2186.77 4978.77,2187 5202,2187 5234.51,2154.49 v1(5234.51,2148.69)
  Signal Layer 6 w5: v1(5234.51,2148.69) 5240.31,2148.69 5288.83,2100.17 5288.83,1537.27 5260.83,1509.27 5260.83,1383.27 v1(5283.83,1360.27)
MCU_GPIO83: EC2.150 U1.D12 | length 3319.2
  Top Layer w5: U1.D12@3600.06,2236.02 v2(3615.8,2251.77)
  Signal Layer 3 w5: v1(3675,2468) 3675,2492.19 3694.58,2511.77 3743.5,2511.77 3764.95,2533.22 3831.65,2533.22 3839.1,2525.77 3988.14,2525.77 4019.13,2494.77 5219.33,2494.77 v1(5231.83,2482.27)
  Signal Layer 6 w5: v1(5231.83,2482.27) 5231.33,2481.77 5231.33,2438.77 5159.83,2367.27 5159.83,2173.27 5203,2130.1 5203,2129.56 5226,2106.56 5226,1422 5242.83,1405.17 5242.83,1342.6 v1(5283.83,1301.6)
  Bottom w5: v2(3615.8,2251.77) 3631.3,2267.27 3631.3,2424.3 v1(3675,2468) ; v1(5283.83,1301.6) 5301.33,1284.1 5301.33,1139.17 EC2.150@5297.43,1135.27
MCU_GPIO84: EC2.151 R63.1 U1.D9 | length 3106.2
  Top Layer w5: U1.D9@3505.57,2236.02 v2@3520.87,2251.32 ; EC2.151@5328.92,1135.27 5328.92,1259.36 v1@5341.83,1272.27
  Signal Layer 3 w5: v2(3521.31,2251.77) 3536.81,2236.27 3685.21,2236.27 3694.83,2236.27 3724.68,2206.42 3757.6,2173.5 3884.5,2173.5 3897,2186 4090.82,2186 4160.59,2255.78 4256.32,2255.78 4316.32,2195.77 4974.81,2195.77 4975.04,2196 5224,2196 v1(5247,2173)
  Signal Layer 6 w5: v1(5247,2173) 5297.83,2122.17 5297.83,1529.27 5269.83,1501.27 5269.83,1451.54 5305.83,1415.54 5305.83,1304.27 v1(5337.83,1272.27)
  Bottom w5: R63.1@5152.94,2274.38 5150.83,2272.27 5150.83,2248.79 5226.62,2173 v1(5247,2173)
MCU_GPIO85: EC2.152 U1.C9 | length 3059.5
  Top Layer w5: U1.C9@3505.57,2267.52 v2(3521.31,2283.26)
  Signal Layer 3 w5: v2(3521.31,2283.26) 3543.82,2305.77 3865.33,2305.77 3879.83,2291.27 3967.73,2291.27 3980.73,2278.27 4021.27,2278.27 4049.17,2306.17 4264.46,2306.17 4297.29,2339 4872,2339 4888.81,2322.19 4932.58,2322.19 5069.17,2322.19 5069.58,2321.77 5084.08,2321.77 5084.5,2322.19 5231.91,2322.19 5310.83,2243.27 v1(5310.83,2240.27)
  Signal Layer 6 w5: v1(5310.83,2240.27) 5307.83,2237.27 5307.83,1526.54 5278.83,1497.54 5278.83,1455.27 5314.83,1419.27 5314.83,1353.94 v1(5337.83,1330.94)
  Bottom w5: EC2.152@5328.92,1135.27 5324.33,1139.86 5324.33,1257.02 5313.83,1267.52 5313.83,1306.94 v1(5337.83,1330.94)
MCU_GPIO86: EC2.153 U1.B9 | length 3589.8
  Top Layer w5: U1.B9@3505.57,2299.01 3521.69,2315.13 3521.69,2356.38 3556.33,2391.02 3556.33,2506.33 v1(3557,2507) ; v1@5343.83,1298.27 5360.42,1281.68 EC2.153@5360.42,1135.27
  Signal Layer 3 w5: v1(3557,2507) 3559.78,2507 3697.55,2644.77 4258.38,2644.77 4324.88,2578.27 5327.67,2578.27 5338.4,2589 v1(5343,2589)
  Signal Layer 6 w5: v1(5337.83,1301.6) 5358.37,1322.14 5358.37,2251.73 5326.94,2283.16 5326.94,2572.94 v1(5343,2589)
MCU_GPIO87: EC2.154 U1.A9 | length 3660.8
  Top Layer w5: v1(3491.63,2437.3) 3491.63,2436.77 3511.83,2416.57 3511.83,2362.36 3505.57,2356.1 U1.A9@3505.57,2330.51
  Signal Layer 3 w5: v1(3491.63,2437.3) 3501.86,2437.3 3514.83,2450.27 3514.83,2548.83 3577.5,2611.5 3648.35,2611.5 3690.62,2653.77 4520.08,2653.77 4534.31,2668 v1(5318,2668)
  Signal Layer 6 w5: v1(5318,2668) 5317.94,2667.94 5317.94,2279.44 5348.33,2249.04 5348.33,1379.76 v1(5333.47,1364.9)
  Bottom w5: v1(5333.47,1364.9) 5361.33,1337.05 5361.33,1136.18 EC2.154@5360.42,1135.27
MCU_GPIO88: EC2.155 U1.B6 | length 3538.7
  Top Layer w5: U1.B6@3411.08,2299.01 3394.54,2315.55 3394.96,2315.96 3394.96,2362.39 3403,2370.44 3403,2409.44 3427.45,2433.89 v1(3432.54,2433.89) ; EC2.155@5391.91,1135.27 5391.91,1240.19 5382.33,1249.77 5382.33,1311.09 v1(5402.04,1330.8)
  Signal Layer 3 w5: v1(3432.54,2433.89) 3445,2421.43 3445,2380.9 3475.44,2350.45 3586.4,2350.45 3715.47,2479.52 3795.56,2479.52 3801.31,2473.77 4242.27,2473.77 4256.77,2459.27 5320.83,2459.27 v1(5347.83,2432.27)
  Signal Layer 6 w5: v1(5347.83,2432.27) 5347.83,2429.02 5376.37,2400.48 5376.37,1356.47 v1(5402.04,1330.8)
MCU_GPIO89: EC2.156 U1.C6 | length 3477.8
  Top Layer w5: v2(3395.33,2283.26) U1.C6@3411.08,2267.52
  Signal Layer 3 w5: v1(3384.42,2385.68) 3428.65,2341.45 3608.02,2341.45 3701.56,2435 3720.45,2435 3737.72,2452.27 4237.83,2452.27 4251.33,2438.77 5169.33,2438.77 5191.83,2416.27 5332.4,2416.27 5344.4,2404.27 v1(5345.83,2404.27)
  Signal Layer 6 w5: v1(5345.83,2404.27) 5346.29,2404.27 5367.37,2383.19 5367.37,1335.98 v1@5399.83,1303.52
  Bottom w5: v1@3388.36,2385.68 3388.36,2346.15 3395.33,2339.18 v2(3395.33,2283.26) ; EC2.156@5391.91,1135.27 5391.91,1222.19 5378.83,1235.27 5378.83,1277.27 5402.04,1300.48 v1(5402.04,1301.54)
